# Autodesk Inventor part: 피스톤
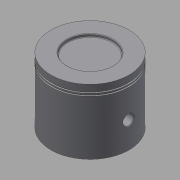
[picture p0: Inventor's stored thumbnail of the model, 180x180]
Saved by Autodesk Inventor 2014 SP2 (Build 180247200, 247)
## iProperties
Created: 2016-11
Part Number: 피스톤
Material: 강철, 탄소
Document SubType Name: Modeling
Designer: mduedu
Density: 7.87 g/cm^3
Mass: 410.128 g
Surface Area: 237.507 cm^2
Volume: 52.1129 cm^3
Appearance: 기본값
Author: mduedu
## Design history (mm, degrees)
sketch "스케치1"
  geometry: C1 r 30 at (0, 0); 1 further point
  constraints: 1 centre point, 1 coincident
  dimensions: "d0" = 60 diameter of C1
extrude "돌출1" new body sketch "스케치1" distance "d1" = 50; taper "d2" = 0 deg
sketch "스케치2"
  geometry: C1 r 28 at (0, 0); 1 further point
  constraints: 1 centre point, 1 coincident
  dimensions: "d3" = 56 diameter of C1
extrude "돌출2" cut sketch "스케치2" distance "d4" = 45; taper "d5" = 0 deg
sketch "스케치3"
  geometry: L1 (30, 0)-(30, 50) reference; L2 (30, 45)-(29, 45); L3 (29, 45)-(29, 44); L4 (29, 44)-(30, 44); L5 (30, 44)-(30, 45); L6 (30, 43)-(29, 43); L7 (29, 43)-(29, 42); L8 (29, 42)-(30, 42); L9 (30, 42)-(30, 43); L10 (30, 50)-(-30, 50) reference; L11 (0, 50)-(0, 0)
  constraints: 18 end point, 4 parallel, 3 equal length, 3 perpendicular, 2 horizontal, 2 point on line, 1 midpoint
  dimensions: "d6" = 1 distance of L2.start L2.end; "d8" = 5 distance between parallel lines of L10 L2; "d9" = 1 distance between parallel lines of L6 L4
revolve "회전1" sketch "스케치3" stored, may be unused: angle "d10" = 90 deg
node "작업 평면1"
sketch "스케치4"
  geometry: L1 (0, -22.978)-(45, -22.978) reference; L2 (45, -22.978)-(45, 22.978) reference; L3 (45, 22.978)-(0, 22.978) reference; L4 (0, 22.978)-(0, 25.377) reference; L5 (0, 25.377)-(42, 25.377) reference; L6 (42, 25.377)-(42, 24.187) reference; L7 (42, 24.187)-(43, 24.187) reference; L8 (43, 24.187)-(43, 25.377) reference; L9 (43, 25.377)-(44, 25.377) reference; L10 (44, 25.377)-(44, 24.187) reference; L11 (44, 24.187)-(45, 24.187) reference; L12 (45, 24.187)-(45, 25.377) reference; L13 (45, 25.377)-(50, 25.377) reference; L14 (50, 25.377)-(50, -25.377) reference; L15 (50, -25.377)-(45, -25.377) reference; L16 (45, -25.377)-(45, -24.187) reference; L17 (45, -24.187)-(44, -24.187) reference; L18 (44, -24.187)-(44, -25.377) reference; L19 (44, -25.377)-(43, -25.377) reference; L20 (43, -25.377)-(43, -24.187) reference; L21 (43, -24.187)-(42, -24.187) reference; L22 (42, -24.187)-(42, -25.377) reference; L23 (42, -25.377)-(0, -25.377) reference; L24 (0, -25.377)-(0, -22.978) reference; L25 (12.5, 22.978)-(45, 22.978); L26 (45, 22.978)-(45, -22.978); L27 (45, -22.978)-(12.5, -22.978); L28 (12.5, -22.978)-(12.5, 22.978); C1 r 7.5 at (20, 0); C2 r 4 at (20, 0); 1 further point
  constraints: 8 end point, 2 centre point, 2 parallel, 1 coincident, 1 horizontal, 1 horizontal alignment, 1 perpendicular, 1 point on line, 1 tangent
  dimensions: "d12" = 15 diameter of C1; "d13" = 8 diameter of C2; "d14" = 20 distance of point (0, 0) C1.centre
  node "절단 모서리 투영1"
extrude "돌출3" join sketch "스케치4" stored distance "d15" = 11.75; taper "d16" = 0 deg
extrude "돌출4" cut sketch "스케치4" stored distance "d17" = 72; taper "d18" = 0 deg
fillet "모깎기2" dims "d20" = 3
chamfer "모따기1" distance "d21" = 0.5; stored, may be unused: second distance "d22" = 2, angle "d23" = 45 deg
chamfer "모따기2" distance "d24" = 0.5; stored, may be unused: second distance "d25" = 2, angle "d26" = 45 deg
sketch "스케치5"
  geometry: C1 r 17.5 at (0, 0); 1 further point
  constraints: 1 centre point, 1 coincident
  dimensions: "d27" = 35 diameter of C1
extrude "돌출5" cut sketch "스케치5" distance "d28" = 2; taper "d29" = 0 deg
fillet "모깎기3" dims "d30" = 0.5
node "솔리드1"
mirror "대칭1"
other parameters: "d11" = -16
